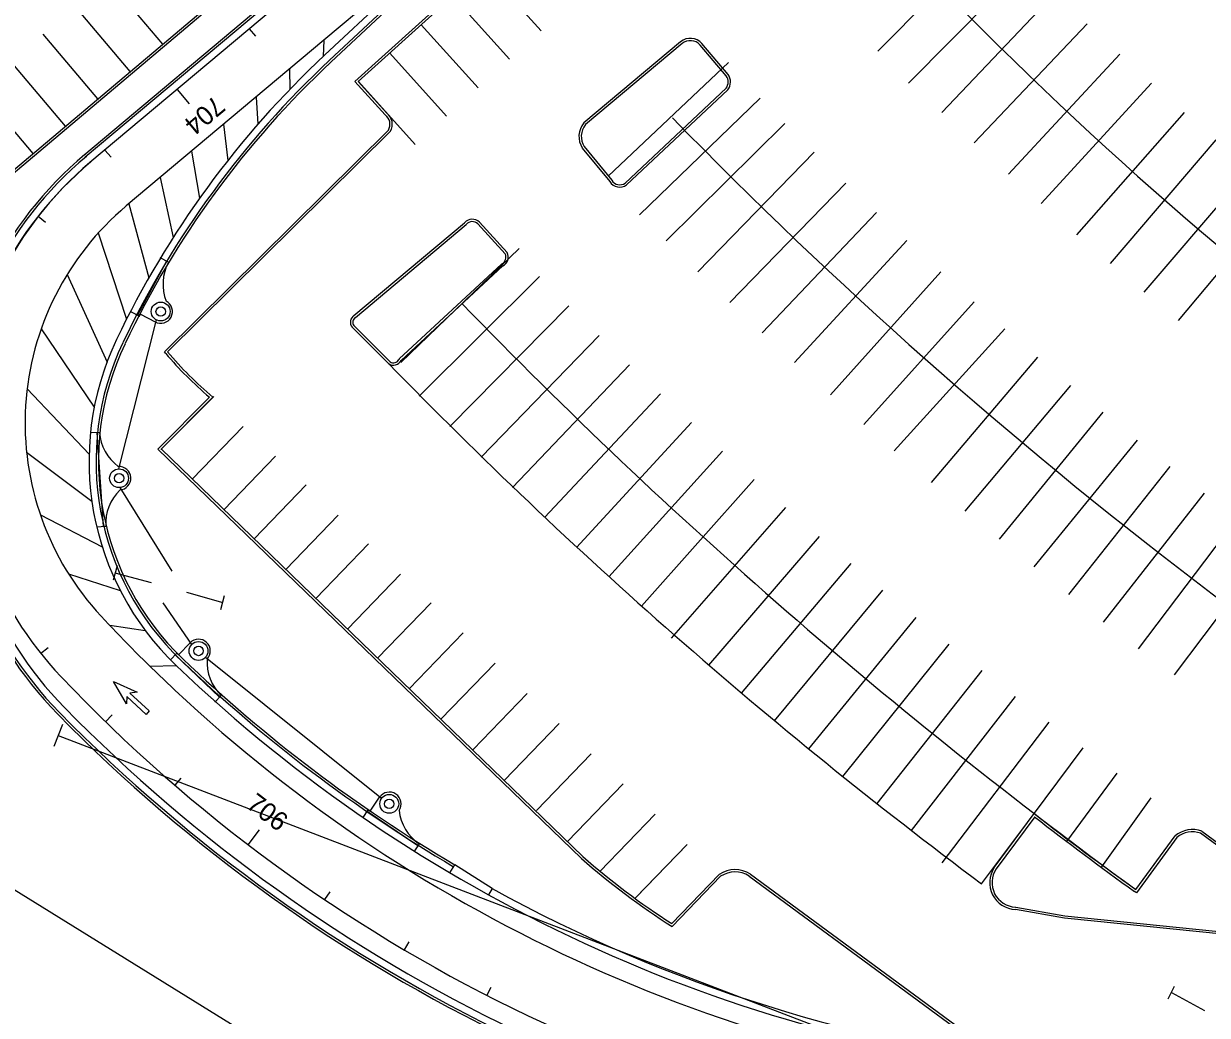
# Model space of a CAD drawing. Extents: x 468143 to 491361, y 1438528 to 1468730.
# Drawn here: x 487470 to 487721.1, y 1467373.9 to 1467584.3 of the extents above; entities that cross this region are included whole.
import ezdxf

# ---------------------------------------------------------------- set-up
doc = ezdxf.new("R2010")
doc.units = 0
doc.layers.add('Default', color=7, linetype='Continuous')
doc.layers.add('Xreference_dp', color=7, linetype='Continuous')

# ---------------------------------------------------------------- blocks, each defined once
blk = doc.blocks.new('POINT_DISPLAY')
at = {"layer": 'Default'}
blk.add_line((0, 0), (0, 0), dxfattribs=at)
blk = doc.blocks.new('DAMerge_2')
at = {"layer": 'Default'}
blk.add_lwpolyline([(0.71, -4.09), (0, -3.39), (3.95, 0.56), (2.42, 0.68), (7.31, 3.21), (4.77, -1.68), (4.66, -0.15), (0.71, -4.09)], dxfattribs=at)
blk = doc.blocks.new('DAMerge_6')
at = {"layer": 'Default'}
blk.add_lwpolyline([(0.71, -4.09), (0, -3.39), (3.95, 0.56), (2.42, 0.68), (7.31, 3.21), (4.77, -1.68), (4.66, -0.15), (0.71, -4.09)], dxfattribs=at)

msp = doc.modelspace()

# ---------------------------------------------------------------- linework, layer by layer
at = {"layer": 'Xreference_dp'}
for p, q in [((487578.33, 1467634.05), (487484.02, 1467554.84)), ((487578.33, 1467634.05), (487484.02, 1467554.84)), ((487578.33, 1467634.05), (487484.02, 1467554.84)), ((487572.45, 1467631.72), (487482.73, 1467556.37)), ((487572.77, 1467631.34), (487483.05, 1467555.99)), ((487586.04, 1467624.86), (487533.64, 1467580.84)), ((487568.58, 1467610.19), (487533.87, 1467577.7)), ((487569.61, 1467609.1), (487534.89, 1467576.6)), ((487569.95, 1467608.73), (487535.23, 1467576.24)), ((487651.19, 1467578.47), (487675.91, 1467603.38)), ((487567.71, 1467596.17), (487579.76, 1467582.8)), ((487657.73, 1467571.71), (487682.55, 1467596.81)), ((487499.47, 1467580.01), (487487.84, 1467593.75)), ((487664.77, 1467565.45), (487688.8, 1467590.77)), ((487561.03, 1467590.15), (487573.08, 1467576.77)), ((487492.59, 1467574.2), (487480.97, 1467587.94)), ((487517.84, 1467583.24), (487519.13, 1467581.71)), ((487554.34, 1467584.12), (487566.39, 1467570.75)), ((487671.66, 1467559.04), (487695.62, 1467584.3)), ((487485.72, 1467568.39), (487474.1, 1467582.13)), ((487533.64, 1467580.84), (487491.74, 1467545.65)), ((487533.64, 1467580.84), (487533.53, 1467577.38)), ((487547.66, 1467578.1), (487559.71, 1467564.73)), ((487478.86, 1467562.58), (487467.23, 1467576.33)), ((487594, 1467551.96), (487619.52, 1467576.09)), ((487678.95, 1467552.38), (487702.59, 1467577.83)), ((487526.34, 1467574.71), (487526.42, 1467570.36)), ((487540.98, 1467572.06), (487553.03, 1467558.69)), ((487685.88, 1467546.17), (487709.29, 1467571.73)), ((487471.98, 1467556.77), (487460.36, 1467570.51)), ((487502.52, 1467570.38), (487505.1, 1467567.32)), ((487519.27, 1467568.77), (487519.67, 1467562.98)), ((487600.62, 1467543.8), (487626.22, 1467568.5)), ((487606.28, 1467538.22), (487631.5, 1467563.17)), ((487693.43, 1467539.54), (487716.3, 1467565.49)), ((487512.37, 1467562.98), (487513.29, 1467555.29)), ((487700.56, 1467533.41), (487722.99, 1467559.66)), ((487487.21, 1467557.52), (487488.5, 1467555.99)), ((487505.6, 1467557.29), (487507.29, 1467547.28)), ((487613.02, 1467531.67), (487637.69, 1467557.05)), ((487707.75, 1467527.34), (487730.14, 1467553.55)), ((487498.91, 1467551.67), (487501.71, 1467538.99)), ((487619.81, 1467525.18), (487644.42, 1467550.5)), ((487492.26, 1467546.09), (487496.54, 1467530.43)), ((487714.98, 1467521.35), (487737.07, 1467547.75)), ((487473.06, 1467543.46), (487474.63, 1467542.23)), ((487626.66, 1467518.76), (487650.96, 1467544.27)), ((487485.8, 1467539.93), (487491.8, 1467521.62)), ((487633.56, 1467512.4), (487657.33, 1467538.31)), ((487550.01, 1467512.44), (487575.09, 1467536.62)), ((487500.25, 1467533.95), (487494.1, 1467522.49)), ((487500.69, 1467533.71), (487498.93, 1467534.66)), ((487479.2, 1467531.12), (487487.65, 1467512.53)), ((487553.91, 1467505.26), (487579.4, 1467530.68)), ((487641.15, 1467505.55), (487664.61, 1467531.64)), ((487492.77, 1467523.2), (487494.54, 1467522.26)), ((487560.37, 1467498.83), (487585.65, 1467524.46)), ((487648.27, 1467499.25), (487671.68, 1467525.28)), ((487498.09, 1467521.48), (487490.08, 1467489.86)), ((487494.54, 1467522.26), (487494.77, 1467522.7)), ((487494.77, 1467522.7), (487497.86, 1467521.04)), ((487473.69, 1467519.59), (487484.93, 1467502.92)), ((487567.01, 1467492.34), (487592.07, 1467518.18)), ((487654.65, 1467493.7), (487678.15, 1467519.59)), ((487662.59, 1467486.93), (487685.14, 1467513.53)), ((487573.71, 1467485.9), (487598.55, 1467511.96)), ((487470.7, 1467506.82), (487483.85, 1467492.99)), ((487580.46, 1467479.52), (487605.07, 1467505.79)), ((487669.75, 1467480.85), (487692.18, 1467507.57)), ((487498.44, 1467494.05), (487509.39, 1467505.06)), ((487499.15, 1467494.05), (487510.31, 1467505.22)), ((487677.05, 1467474.94), (487699.02, 1467501.88)), ((487505.74, 1467487.68), (487516.54, 1467498.88)), ((487587.27, 1467473.2), (487611.65, 1467499.68)), ((487486.05, 1467497.61), (487484.06, 1467497.47)), ((487486.89, 1467477.62), (487485.55, 1467497.57)), ((487684.36, 1467469.05), (487706.3, 1467495.95)), ((487470.58, 1467493.42), (487484.42, 1467483.02)), ((487594.12, 1467466.94), (487618.28, 1467493.62)), ((487512.46, 1467481.19), (487523.42, 1467492.56)), ((487691.73, 1467463.22), (487713.26, 1467490.38)), ((487490.35, 1467485.87), (487501.4, 1467468.16)), ((487518.85, 1467475.02), (487529.88, 1467486.46)), ((487601.03, 1467460.74), (487624.96, 1467487.63)), ((487699.06, 1467457.36), (487720.5, 1467484.7)), ((487607.42, 1467453.95), (487631.69, 1467481.69)), ((487706.52, 1467451.65), (487728.29, 1467480.53)), ((487473.52, 1467480.08), (487486.65, 1467473.28)), ((487487.39, 1467477.65), (487485.4, 1467477.52)), ((487525.57, 1467468.53), (487536.68, 1467480.05)), ((487525.57, 1467468.53), (487536.68, 1467480.05)), ((487615.36, 1467448.21), (487638.82, 1467475.51)), ((487531.96, 1467462.35), (487543.14, 1467473.95)), ((487714.14, 1467446.16), (487734.92, 1467473.73)), ((487489.8, 1467469.26), (487488.96, 1467466.21)), ((487497.12, 1467465.69), (487489.38, 1467467.73)), ((487622.3, 1467442.29), (487645.54, 1467469.79)), ((487479.49, 1467467.57), (487490.46, 1467464.05)), ((487538.67, 1467455.86), (487549.93, 1467467.54)), ((487538.67, 1467455.86), (487549.93, 1467467.54)), ((487504.52, 1467463.7), (487512.2, 1467461.47)), ((487511.79, 1467459.98), (487512.61, 1467462.97)), ((487629.3, 1467436.42), (487652.3, 1467464.12)), ((487505.63, 1467452.59), (487499.59, 1467461.4)), ((487545.06, 1467449.69), (487556.4, 1467461.44)), ((487374.27, 1467458.66), (487518.88, 1467369.05)), ((487636.6, 1467430.42), (487659.36, 1467458.31)), ((487488.27, 1467456.66), (487495.74, 1467455.57)), ((487551.78, 1467443.2), (487563.19, 1467455.03)), ((487502.85, 1467450.41), (487505.27, 1467452.94)), ((487643.81, 1467424.58), (487666.33, 1467452.67)), ((487473.57, 1467450.7), (487475.14, 1467451.95)), ((487501.1, 1467449.31), (487502.49, 1467450.75)), ((487511.54, 1467441.41), (487502.14, 1467450.39)), ((487502.49, 1467450.75), (487502.85, 1467450.41)), ((487496.74, 1467447.97), (487502.36, 1467448.1)), ((487545.88, 1467419.88), (487508.52, 1467449.83)), ((487558.49, 1467436.71), (487569.98, 1467448.62)), ((487651.08, 1467418.81), (487673.36, 1467447.09)), ((487511.88, 1467441.77), (487510.5, 1467440.32)), ((487565.31, 1467430.33), (487576.77, 1467442.22)), ((487658.38, 1467413.1), (487680.42, 1467441.57)), ((487487.33, 1467436.2), (487488.72, 1467437.64)), ((487478.24, 1467435.64), (487476.37, 1467430.97)), ((487571.92, 1467423.74), (487583.57, 1467435.81)), ((487664.83, 1467406.28), (487687.53, 1467436.12)), ((487477.3, 1467433.31), (487755.04, 1467326.77)), ((487684.01, 1467416.22), (487694.79, 1467430.64)), ((487578.75, 1467417.37), (487590.36, 1467429.4)), ((487691.33, 1467410.8), (487701.99, 1467425.31)), ((487502.08, 1467422.7), (487503.38, 1467424.22)), ((487585.35, 1467410.76), (487597.15, 1467422.99)), ((487543.51, 1467417.25), (487545.47, 1467420.16)), ((487698.71, 1467405.43), (487709.24, 1467420.03)), ((487541.98, 1467415.87), (487543.1, 1467417.53)), ((487543.1, 1467417.53), (487543.51, 1467417.25)), ((487553.6, 1467409.86), (487542.82, 1467417.12)), ((487592.19, 1467404.4), (487603.94, 1467416.58)), ((487673.24, 1467401.8), (487684.01, 1467416.22)), ((487517.61, 1467410.1), (487520.03, 1467413.28)), ((487553.88, 1467410.27), (487552.76, 1467408.61)), ((487599.69, 1467398.72), (487610.73, 1467410.17)), ((487599.95, 1467399), (487610.73, 1467410.17)), ((487560.42, 1467404.13), (487561.44, 1467405.85)), ((487569.36, 1467400.8), (487561.44, 1467405.85)), ((487607.5, 1467393.37), (487617.53, 1467403.77)), ((487533.85, 1467398.44), (487534.97, 1467400.1)), ((487569.36, 1467400.8), (487568.62, 1467399.45)), ((487550.76, 1467387.77), (487551.78, 1467389.49)), ((487568.27, 1467378.11), (487569.19, 1467379.89)), ((487712.84, 1467377.39), (487714.15, 1467380.05)), ((487713.49, 1467378.72), (487720.53, 1467374.91))]:
    msp.add_line(p, q, dxfattribs=at)
for points in [[(487546.7, 1467564.97), (487546.66, 1467564.99), (487540.27, 1467572.08), (487591.74, 1467618.55), (487668.91, 1467686.29), (487680.42, 1467672.59)], [(487599.77, 1467685.11), (487610.22, 1467672.75), (487458.19, 1467544.45)], [(487599.32, 1467684.87), (487609.52, 1467672.8), (487458.25, 1467545.15), (487458.25, 1467545.15), (487458.25, 1467545.15), (487458.25, 1467545.15)], [(487547, 1467565.36), (487540.97, 1467572.04), (487592.08, 1467618.18), (487668.86, 1467685.57), (487680.44, 1467671.79)], [(487609.36, 1467580.5), (487588.81, 1467563.27)], [(487609.67, 1467580.11), (487589.17, 1467562.92)], [(487619.04, 1467573.25), (487613.5, 1467579.8)], [(487619.43, 1467573.55), (487613.88, 1467580.13)], [(487597.58, 1467550.51), (487619.03, 1467570.65)], [(487597.9, 1467550.12), (487619.4, 1467570.32)], [(487500.12, 1467514.35), (487499.82, 1467514.71), (487547.36, 1467561.77)], [(487500.5, 1467514.68), (487547.76, 1467561.46)], [(487588.9, 1467558.24), (487594.75, 1467551.13), (487594.76, 1467551.1)], [(487588.49, 1467557.95), (487594.34, 1467550.84)], [(487540.05, 1467522.41), (487563.54, 1467542.1)], [(487540.33, 1467522), (487540.35, 1467522.01), (487563.89, 1467541.73), (487563.91, 1467541.76)], [(487566.32, 1467541.88), (487572.15, 1467535.48)], [(487566.67, 1467542.24), (487572.57, 1467535.76)], [(487571.36, 1467533.32), (487549.65, 1467513.18), (487549.61, 1467513.09)], [(487571.65, 1467532.91), (487550.06, 1467512.88)], [(487571.43, 1467533.35), (487571.36, 1467533.32)], [(487547.4, 1467512.22), (487539.64, 1467519.94)], [(487547.72, 1467512.6), (487540.02, 1467520.27)], [(487550.06, 1467512.88), (487550.06, 1467512.88)], [(487499.09, 1467494), (487499.09, 1467494), (487510.13, 1467505.09)], [(487588.32, 1467407.19), (487588.31, 1467407.2), (487498.44, 1467494.05)], [(487588.65, 1467407.57), (487499.12, 1467494.08)], [(487675.91, 1467405.25), (487684.39, 1467416.73)], [(487684.49, 1467416.02), (487676.32, 1467404.96)], [(487747.46, 1467392.13), (487719.71, 1467412.54)], [(487719.95, 1467412.98), (487747.84, 1467392.47)], [(487714.64, 1467411.62), (487706.07, 1467399.9), (487705.66, 1467400.18)], [(487705.95, 1467400.59), (487714.28, 1467411.97)], [(487607.5, 1467393.37), (487617.54, 1467403.78)], [(487607.57, 1467392.73), (487617.86, 1467403.39)], [(487623.93, 1467403.42), (487670.05, 1467369.49)], [(487624.21, 1467403.83), (487670.24, 1467369.96), (487670.24, 1467369.96)], [(487747.42, 1467388.75), (487690.8, 1467394.51), (487680.41, 1467396.37)], [(487680.43, 1467396.87), (487680.46, 1467396.87), (487690.87, 1467395.01), (487747.21, 1467389.28)]]:
    msp.add_lwpolyline(points, dxfattribs=at)
for centre, radius in [((487499.04, 1467523.24), 2), ((487499.04, 1467523.24), 1), ((487490.21, 1467487.87), 2), ((487490.21, 1467487.87), 1), ((487507.07, 1467451.21), 2), ((487507.07, 1467451.21), 1), ((487547.54, 1467418.76), 2), ((487547.54, 1467418.76), 1)]:
    msp.add_circle(centre, radius, dxfattribs=at)
for centre, radius, start, end in [((488316.54, 1468252.52), 868.53, 224.21057, 241.70258), ((488249.41, 1468160.65), 815.72, 222.86411, 243.14977), ((487611.43, 1467577.94), 3.29, 41.8448, 128.9202), ((487611.43, 1467577.94), 2.79, 41.9883, 128.8302), ((487671.61, 1467430.55), 201.56, 133.1076, 154.5106), ((487671.61, 1467430.55), 200.06, 133.1076, 154.5106), ((487671.61, 1467430.55), 199.56, 133.1076, 154.5106), ((487617.23, 1467571.96), 2.22, 323.9755, 35.4728), ((487617.23, 1467571.96), 2.72, 322.9324, 35.9272), ((487545.2, 1467562.99), 2.48, 330.4534, 52.7665), ((487545.2, 1467562.99), 2.98, 329.0646, 52.7665), ((487592.37, 1467560.39), 4.58, 141.0679, 212.1824), ((488329.19, 1468267.3), 1007.37, 224.24997, 241.11149), ((487592.37, 1467560.39), 4.08, 141.7299, 211.7526), ((487535.04, 1467494.52), 81, 130.0267, 224.4359), ((487535.04, 1467494.52), 80.5, 130.0267, 224.4359), ((487535.04, 1467494.52), 79, 130.0267, 224.4359), ((487532.25, 1467497.41), 75, 130.0267, 223.5592), ((487532.25, 1467497.41), 75, 130.0266, 223.5591), ((487596.44, 1467552.1), 2.46, 210.9853, 306.3659), ((487596.44, 1467552.1), 1.96, 210.9853, 305.5407), ((487530.43, 1467499.58), 60.16, 130.0266, 222.9389), ((487565.18, 1467540.59), 2.23, 47.9268, 137.3153), ((487565.18, 1467540.59), 1.73, 48.6876, 137.3153), ((487570.71, 1467534.79), 1.6, 296.6279, 25.4458), ((487570.71, 1467534.79), 2.1, 296.6279, 27.6007), ((487509.54, 1467529.06), 10, 152.3285, 201.219), ((487499.04, 1467523.24), 2.5, 241.7568, 61.7568), ((488359.78, 1468296.83), 1109.39, 224.09472, 233.88831), ((487541.04, 1467520.98), 1.74, 124.6689, 216.5585), ((487541.04, 1467520.98), 1.24, 124.6689, 214.9714), ((487543.83, 1467491.46), 60, 154.5106, 226.2873), ((487543.83, 1467491.46), 58.5, 154.5106, 226.2873), ((487543.83, 1467491.46), 58, 154.5106, 226.2873), ((487561.76, 1467566.63), 80.83, 220.2999, 229.6167), ((487561.76, 1467566.63), 80.33, 220.2999, 230.0024), ((487548.47, 1467513.61), 1.75, 232.2405, 335.3471), ((487548.47, 1467513.61), 1.25, 233.544, 335.3471), ((488305.17, 1468248.92), 1056.86, 224.19208, 233.27794), ((487496.02, 1467498.38), 10, 184.4123, 233.3028), ((487490.21, 1467487.87), 2.5, 273.8407, 93.8407), ((487497.37, 1467478.22), 10, 134.3785, 183.269), ((487722.14, 1467677.97), 322.03, 222.9389, 226.2873), ((487507.07, 1467451.21), 2.5, 316.2873, 136.2873), ((487722.14, 1467677.97), 318.03, 226.2873, 264.1733), ((487722.14, 1467677.97), 316.53, 226.2873, 239.4368), ((487722.14, 1467677.97), 316.03, 226.2873, 239.4368), ((487518.86, 1467448.93), 10, 176.8251, 225.7156), ((487722.14, 1467677.97), 337.03, 223.5592, 264.1733), ((487722.14, 1467677.97), 337.03, 223.5591, 264.1733), ((487722.14, 1467677.97), 322.03, 226.2873, 264.1733), ((487722.14, 1467677.97), 343.03, 224.4359, 264.1733), ((487722.14, 1467677.97), 342.53, 224.4359, 264.1733), ((487722.14, 1467677.97), 341.03, 224.4359, 264.1733), ((487547.54, 1467418.76), 2.5, 326.0368, 146.0368), ((487559.55, 1467418.51), 10, 186.5747, 235.4652), ((488101.93, 1467952.3), 679.11, 232.05933, 234.3318), ((488101.93, 1467952.3), 679.61, 232.10258, 234.3318), ((487717.99, 1467407.61), 5.72, 69.9126, 130.4194), ((487717.99, 1467407.61), 5.22, 70.6787, 129.7895), ((487692.74, 1467526.1), 157.75, 228.7106, 237.2895), ((487692.74, 1467526.1), 158.25, 228.7106, 237.4381), ((487620.91, 1467398.89), 5.94, 56.2566, 124.6228), ((487680.63, 1467402.06), 5.7, 146.0334, 267.7108), ((487680.63, 1467402.06), 5.2, 146.1505, 267.7108), ((487620.91, 1467398.89), 5.44, 56.3734, 124.1082), ((487722.14, 1467677.97), 316.49, 241.1368, 264.1733)]:
    msp.add_arc(centre, radius, start, end, dxfattribs=at)

# ---------------------------------------------------------------- block references
for name, p, rotation in [('POINT_DISPLAY', (487494.19, 1467525.85), -118.24319519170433), ('POINT_DISPLAY', (487494.19, 1467525.85), -118.24319519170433), ('POINT_DISPLAY', (487497.05, 1467523.46), -118.24319519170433), ('POINT_DISPLAY', (487497.28, 1467524.19), -118.24319519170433), ('POINT_DISPLAY', (487497.28, 1467524.19), -118.24319519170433), ('POINT_DISPLAY', (487497.81, 1467524.82), -118.24319519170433), ('POINT_DISPLAY', (487498.49, 1467525.17), -118.24319519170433), ('POINT_DISPLAY', (487499.04, 1467523.24), -118.24319519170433), ('POINT_DISPLAY', (487499.04, 1467523.24), -118.24319519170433), ('POINT_DISPLAY', (487499.25, 1467525.23), -118.24319519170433), ('POINT_DISPLAY', (487499.99, 1467525.01), -118.24319519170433), ('POINT_DISPLAY', (487499.99, 1467525.01), -118.24319519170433), ('POINT_DISPLAY', (487500.62, 1467524.47), -118.24319519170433), ('POINT_DISPLAY', (487500.96, 1467523.79), -118.24319519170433), ('POINT_DISPLAY', (487501.03, 1467523.03), -118.24319519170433), ('POINT_DISPLAY', (487497.12, 1467522.69), -118.24319519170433), ('POINT_DISPLAY', (487497.46, 1467522.01), -118.24319519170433), ('POINT_DISPLAY', (487498.09, 1467521.48), -118.24319519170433), ('POINT_DISPLAY', (487498.09, 1467521.48), -118.24319519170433), ('POINT_DISPLAY', (487498.82, 1467521.25), -118.24319519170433), ('POINT_DISPLAY', (487499.59, 1467521.32), -118.24319519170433), ('POINT_DISPLAY', (487500.27, 1467521.67), -118.24319519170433), ('POINT_DISPLAY', (487500.8, 1467522.3), -118.24319519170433), ('POINT_DISPLAY', (487500.8, 1467522.3), -118.24319519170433), ('POINT_DISPLAY', (487501.24, 1467522.06), -118.24319519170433), ('DAMerge_2', (487492.57, 1467437.6), 92.47371323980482), ('DAMerge_6', (487492.57, 1467437.6), 92.47371323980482)]:
    msp.add_blockref(name, p, dxfattribs=dict(at, rotation=rotation))
for p, yscale, rotation in [((487488.22, 1467487.73), -0.9999999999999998, 93.84065932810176), ((487488.22, 1467487.73), -0.9999999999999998, 93.84065932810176), ((487488.31, 1467488.49), -0.9999999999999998, 93.84065932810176), ((487488.69, 1467489.16), -0.9999999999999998, 93.84065932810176), ((487489.29, 1467489.64), -0.9999999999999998, 93.84065932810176), ((487490.08, 1467489.86), -0.9999999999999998, 93.84065932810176), ((487490.08, 1467489.86), -0.9999999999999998, 93.84065932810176), ((487490.21, 1467487.87), -0.9999999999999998, 93.84065932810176), ((487490.21, 1467487.87), -0.9999999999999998, 93.84065932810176), ((487490.84, 1467489.76), -0.9999999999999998, 93.84065932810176), ((487491.51, 1467489.39), -0.9999999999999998, 93.84065932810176), ((487491.99, 1467488.79), -0.9999999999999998, 93.84065932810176), ((487492.21, 1467488), -0.9999999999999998, 93.84065932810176), ((487492.21, 1467488), -0.9999999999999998, 93.84065932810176), ((487492.71, 1467488.03), -0.9999999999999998, 93.84065932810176), ((487484.73, 1467487.5), -0.9999999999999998, 93.84065932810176), ((487484.73, 1467487.5), -0.9999999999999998, 93.84065932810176), ((487488.44, 1467486.94), -0.9999999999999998, 93.84065932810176), ((487488.92, 1467486.34), -0.9999999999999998, 93.84065932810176), ((487489.59, 1467485.97), -0.9999999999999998, 93.84065932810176), ((487490.35, 1467485.87), -0.9999999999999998, 93.84065932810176), ((487490.35, 1467485.87), -0.9999999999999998, 93.84065932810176), ((487491.14, 1467486.09), -0.9999999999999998, 93.84065932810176), ((487491.74, 1467486.57), -0.9999999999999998, 93.84065932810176), ((487492.11, 1467487.24), -0.9999999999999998, 93.84065932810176), ((487505.63, 1467452.59), -0.9999999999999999, 136.28728470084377), ((487505.63, 1467452.59), -0.9999999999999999, 136.28728470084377), ((487506.25, 1467453.03), -0.9999999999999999, 136.28728470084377), ((487507, 1467453.21), -0.9999999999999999, 136.28728470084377), ((487507.75, 1467453.09), -0.9999999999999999, 136.28728470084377), ((487508.45, 1467452.65), -0.9999999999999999, 136.28728470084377), ((487508.45, 1467452.65), -0.9999999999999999, 136.28728470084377), ((487508.8, 1467453.01), -0.9999999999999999, 136.28728470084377), ((487505.07, 1467451.13), -0.9999999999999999, 136.28728470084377), ((487505.19, 1467451.89), -0.9999999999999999, 136.28728470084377), ((487505.25, 1467450.39), -0.9999999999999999, 136.28728470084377), ((487507.07, 1467451.21), -0.9999999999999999, 136.28728470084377), ((487507.07, 1467451.21), -0.9999999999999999, 136.28728470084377), ((487508.9, 1467452.03), -0.9999999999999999, 136.28728470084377), ((487508.95, 1467450.52), -0.9999999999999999, 136.28728470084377), ((487509.07, 1467451.28), -0.9999999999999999, 136.28728470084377), ((487505.69, 1467449.76), -0.9999999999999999, 136.28728470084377), ((487505.69, 1467449.76), -0.9999999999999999, 136.28728470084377), ((487506.39, 1467449.33), -0.9999999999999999, 136.28728470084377), ((487507.15, 1467449.21), -0.9999999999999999, 136.28728470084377), ((487507.89, 1467449.38), -0.9999999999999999, 136.28728470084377), ((487508.52, 1467449.83), -0.9999999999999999, 136.28728470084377), ((487508.52, 1467449.83), -0.9999999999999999, 136.28728470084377), ((487503.27, 1467447.23), -0.9999999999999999, 136.28728470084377), ((487503.27, 1467447.23), -0.9999999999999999, 136.28728470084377), ((487545.88, 1467419.88), -1, 146.03683059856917), ((487545.88, 1467419.88), -1, 146.03683059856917), ((487546.42, 1467420.42), -1, 146.03683059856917), ((487547.13, 1467420.72), -1, 146.03683059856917), ((487547.89, 1467420.73), -1, 146.03683059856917), ((487548.66, 1467420.42), -1, 146.03683059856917), ((487548.66, 1467420.42), -1, 146.03683059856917), ((487548.94, 1467420.83), -1, 146.03683059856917), ((487549.2, 1467419.88), -1, 146.03683059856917), ((487545.57, 1467419.11), -1, 146.03683059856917), ((487545.58, 1467418.35), -1, 146.03683059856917), ((487545.88, 1467417.64), -1, 146.03683059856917), ((487547.54, 1467418.76), -1, 146.03683059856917), ((487547.54, 1467418.76), -1, 146.03683059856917), ((487549.2, 1467417.64), -1, 146.03683059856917), ((487549.2, 1467417.64), -1, 146.03683059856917), ((487549.5, 1467419.17), -1, 146.03683059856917), ((487549.51, 1467418.41), -1, 146.03683059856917), ((487546.42, 1467417.1), -1, 146.03683059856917), ((487546.42, 1467417.1), -1, 146.03683059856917), ((487547.18, 1467416.79), -1, 146.03683059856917), ((487547.95, 1467416.8), -1, 146.03683059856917), ((487548.66, 1467417.1), -1, 146.03683059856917), ((487544.47, 1467414.2), -1, 146.03683059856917), ((487544.47, 1467414.2), -1, 146.03683059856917)]:
    msp.add_blockref('POINT_DISPLAY', p, dxfattribs=dict(at, yscale=yscale, rotation=rotation))

# ---------------------------------------------------------------- texts
for s, rotation, p in [('704', 220.0267, (487510.51, 1467569.25)), ('706', 322.6368, (487516.97, 1467418.14))]:
    msp.add_text(s, height=4, rotation=rotation, dxfattribs=at).set_placement(p)

doc.saveas('drawing.dxf')
